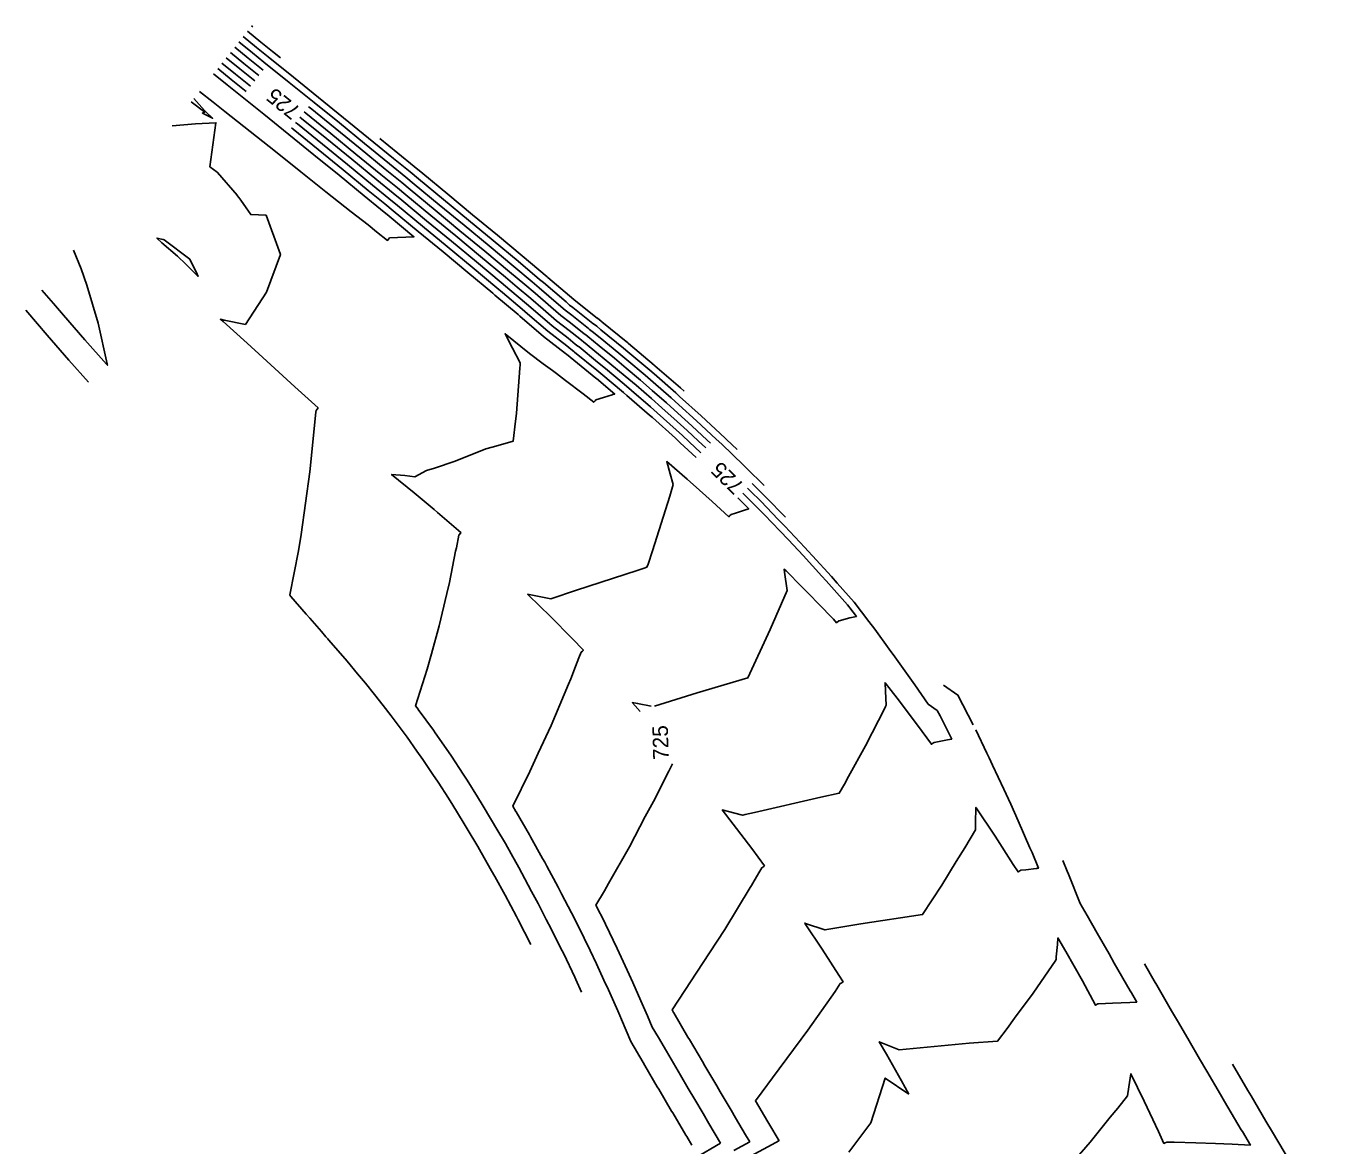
# Model space of a CAD drawing. Extents: x 1487507 to 1489130, y 497211 to 499439.
# Drawn here: x 1488436.5 to 1488637.2, y 499265.5 to 499439 of the extents above; entities that cross this region are included whole.
import ezdxf

# ---------------------------------------------------------------- set-up
doc = ezdxf.new("R2010")
doc.units = 0
for name, color, linetype in [('Prop CMT Ditch DDE', 7, 'Continuous'), ('Prop Drainage Ditch Flow Line', 7, 'Continuous'), ('Prop Drainage Structure Box Number Symbol CELL', 7, 'Continuous')]:
    doc.layers.add(name, color=color, linetype=linetype)

msp = doc.modelspace()

# ---------------------------------------------------------------- linework, layer by layer
at = {"layer": 'Prop CMT Ditch DDE'}
for points in [[(1488470.1, 499437.32), (1488472.2, 499435.62), (1488473.99, 499434.18), (1488477.89, 499431.04), (1488481.78, 499427.9), (1488485.66, 499424.75), (1488489.54, 499421.59), (1488493.41, 499418.43), (1488495.97, 499416.34), (1488497.28, 499415.26), (1488501.14, 499412.08), (1488504.99, 499408.89), (1488508.84, 499405.7), (1488512.68, 499402.5), (1488516.02, 499399.7), (1488516.63, 499399.19), (1488520.12, 499396.19), (1488520.67, 499395.71), (1488521.18, 499395.31), (1488524.28, 499392.88), (1488524.37, 499392.81), (1488524.86, 499392.42), (1488525.52, 499391.88), (1488529, 499389.05), (1488529.67, 499388.48), (1488533.08, 499385.62), (1488533.74, 499385.04), (1488537.1, 499382.11), (1488537.7, 499381.57), (1488541.06, 499378.54), (1488544.77, 499375.08), (1488544.97, 499374.9), (1488546.61, 499373.32)], [(1488471.62, 499438.8), (1488471.41, 499438.97)], [(1488473.22, 499432.1), (1488472.69, 499432.53), (1488470.89, 499433.97), (1488468.8, 499435.67)], [(1488469.45, 499436.49), (1488471.55, 499434.79), (1488473.34, 499433.35), (1488477.24, 499430.22), (1488481.13, 499427.08), (1488485.01, 499423.93), (1488488.89, 499420.77), (1488492.76, 499417.61), (1488495.31, 499415.51), (1488496.62, 499414.43), (1488500.49, 499411.25), (1488504.34, 499408.07), (1488508.19, 499404.87), (1488512.03, 499401.67), (1488514.87, 499399.29), (1488515.97, 499398.37), (1488518.93, 499395.82), (1488520, 499394.9), (1488520.99, 499394.13), (1488523.6, 499392.08), (1488523.76, 499391.95), (1488524.18, 499391.62), (1488525.4, 499390.63), (1488528.3, 499388.26), (1488529.54, 499387.22), (1488532.37, 499384.84), (1488533.6, 499383.76), (1488536.38, 499381.34), (1488537.57, 499380.27), (1488540.33, 499377.78), (1488543.38, 499374.94), (1488544.23, 499374.15), (1488547.61, 499370.89), (1488548.06, 499370.46), (1488550.79, 499367.74)], [(1488471.23, 499429.64), (1488470.72, 499430.05), (1488468.93, 499431.49), (1488466.83, 499433.2)], [(1488468.14, 499434.84), (1488470.24, 499433.14), (1488472.03, 499431.7), (1488472.56, 499431.28)], [(1488465.53, 499431.55), (1488467.62, 499429.84), (1488469.42, 499428.4), (1488473.31, 499425.27), (1488477.2, 499422.13), (1488481.08, 499418.98), (1488484.96, 499415.82), (1488488.83, 499412.66), (1488491.39, 499410.56), (1488492.7, 499409.49), (1488496.56, 499406.31), (1488496.57, 499406.3), (1488496.56, 499406.3), (1488492.79, 499406.11), (1488492.48, 499405.72), (1488490.78, 499407.06), (1488489.45, 499408.12), (1488486.86, 499410.17), (1488482.94, 499413.28), (1488479.03, 499416.38), (1488475.11, 499419.49), (1488471.19, 499422.6), (1488467.27, 499425.7), (1488465.47, 499427.13), (1488463.36, 499428.81)], [(1488466.18, 499432.37), (1488468.28, 499430.67), (1488470.07, 499429.23), (1488470.57, 499428.82)], [(1488462.48, 499427.71), (1488464.15, 499425.85), (1488464.31, 499425.67), (1488465.37, 499424.66), (1488463.8, 499425.46), (1488463.94, 499425.52), (1488464.11, 499425.59), (1488464.13, 499425.6), (1488464.16, 499425.6), (1488462.08, 499427.2)], [(1488479.56, 499425.63), (1488479.82, 499425.43), (1488483.7, 499422.28), (1488487.58, 499419.12), (1488491.45, 499415.96), (1488494, 499413.86), (1488495.32, 499412.78), (1488499.18, 499409.61), (1488503.03, 499406.42), (1488506.88, 499403.22), (1488510.72, 499400.02), (1488512.56, 499398.48), (1488514.65, 499396.73), (1488516.55, 499395.1), (1488518.66, 499393.28), (1488520.61, 499391.75), (1488522.23, 499390.48), (1488522.55, 499390.22), (1488522.81, 499390.02), (1488525.14, 499388.12), (1488526.91, 499386.68), (1488529.27, 499384.7), (1488530.95, 499383.28), (1488533.33, 499381.21), (1488534.94, 499379.8), (1488537.31, 499377.67), (1488538.87, 499376.26), (1488540.59, 499374.66), (1488541.75, 499373.58)], [(1488542.49, 499374.33), (1488541.98, 499374.8), (1488539.6, 499377.02), (1488537.44, 499378.97), (1488535.66, 499380.57), (1488533.47, 499382.48), (1488531.66, 499384.06), (1488529.4, 499385.96), (1488527.6, 499387.47), (1488525.27, 499389.38), (1488523.49, 499390.82), (1488523.16, 499391.09), (1488522.91, 499391.28), (1488520.8, 499392.94), (1488519.33, 499394.09), (1488517.74, 499395.46), (1488515.31, 499397.55), (1488513.71, 499398.89), (1488511.38, 499400.85), (1488507.53, 499404.05), (1488503.69, 499407.24), (1488499.83, 499410.43), (1488495.97, 499413.61), (1488494.66, 499414.69), (1488492.1, 499416.78), (1488488.23, 499419.95), (1488484.35, 499423.1), (1488480.47, 499426.25), (1488480.23, 499426.45)], [(1488459.14, 499423.5), (1488462.75, 499423.8), (1488465.89, 499423.96), (1488464.97, 499417.14), (1488466.09, 499416.3), (1488466.15, 499416.24), (1488469.17, 499412.73), (1488469.19, 499412.71), (1488469.21, 499412.68), (1488469.46, 499412.37), (1488469.76, 499411.96), (1488470.59, 499410.77), (1488471.3, 499409.73), (1488473.67, 499409.63), (1488475.7, 499404.14), (1488475.87, 499403.57), (1488473.71, 499397.69), (1488470.45, 499392.72), (1488467.17, 499393.39), (1488466.6, 499393.52), (1488467, 499393.16), (1488470.71, 499389.8), (1488473.16, 499387.57), (1488474.42, 499386.43), (1488478.13, 499383.06), (1488481.72, 499379.8), (1488481.41, 499379.4), (1488481.39, 499379.13), (1488480.42, 499369.86), (1488479.11, 499360.15), (1488478.67, 499357.65), (1488477.34, 499350.79), (1488477.46, 499350.59), (1488477.5, 499350.53), (1488479.89, 499347.84), (1488480.45, 499347.21), (1488482.23, 499345.12), (1488482.92, 499344.29), (1488483.22, 499343.97), (1488483.33, 499343.83), (1488485.18, 499341.72), (1488486.24, 499340.51), (1488487.84, 499338.59), (1488489.06, 499337.13), (1488490.46, 499335.38), (1488491.8, 499333.68), (1488493.02, 499332.08), (1488494.45, 499330.18), (1488495.49, 499328.74), (1488497.02, 499326.61), (1488497.92, 499325.32), (1488499.51, 499322.99), (1488500.29, 499321.8), (1488501.9, 499319.32), (1488502.59, 499318.22), (1488504.2, 499315.6), (1488504.82, 499314.57), (1488506.43, 499311.84), (1488506.99, 499310.88), (1488508.59, 499308.06), (1488509.1, 499307.15), (1488510.69, 499304.26), (1488512.42, 499300.98), (1488512.72, 499300.43), (1488514.67, 499296.61)], [(1488477.58, 499423.18), (1488477.85, 499422.95), (1488481.74, 499419.8), (1488485.62, 499416.65), (1488489.49, 499413.48), (1488492.04, 499411.39), (1488493.35, 499410.31), (1488497.21, 499407.13), (1488501.07, 499403.94), (1488504.92, 499400.75), (1488508.76, 499397.55), (1488509.1, 499397.26), (1488512.68, 499394.27), (1488512.97, 499394.01), (1488516.64, 499390.85), (1488520.04, 499388.19), (1488520.19, 499388.08), (1488520.74, 499387.63), (1488520.76, 499387.62), (1488524.75, 499384.37), (1488524.82, 499384.31), (1488527.65, 499381.93), (1488527.38, 499381.85), (1488527.25, 499381.81), (1488525.92, 499381.41), (1488524.75, 499381.04), (1488524.61, 499380.89), (1488524.41, 499380.66), (1488522.75, 499381.97), (1488520.04, 499384.03), (1488518.62, 499385.11), (1488518.03, 499385.55), (1488516.59, 499386.61), (1488514.44, 499388.19), (1488510.67, 499391.28), (1488511.83, 499389.04), (1488513, 499386.78), (1488513, 499386.58), (1488512.99, 499386.45), (1488512.95, 499385.94), (1488512.43, 499378.97), (1488512.34, 499378.08), (1488512.31, 499377.73), (1488511.91, 499374.6), (1488508.9, 499373.74), (1488508.66, 499373.68), (1488507.71, 499373.42), (1488502.93, 499371.51), (1488499.72, 499370.45), (1488498.53, 499370.08), (1488496.72, 499369.09), (1488495.15, 499369.3), (1488493.1, 499369.47), (1488496.57, 499366.64), (1488499.7, 499364.01), (1488500.21, 499363.57), (1488503.8, 499360.45), (1488503.83, 499360.43), (1488503.5, 499360.06), (1488503.5, 499360.06), (1488503.13, 499358.12), (1488503.02, 499357.59), (1488502.07, 499352.74), (1488501.66, 499351.01), (1488500.49, 499346), (1488499.28, 499341.68), (1488498.63, 499339.28), (1488496.82, 499333.6), (1488497.19, 499333.11), (1488497.23, 499333.06), (1488499.57, 499329.83), (1488499.84, 499329.45), (1488501.9, 499326.47), (1488502.37, 499325.79), (1488504.19, 499323.02), (1488504.8, 499322.08), (1488506.41, 499319.5), (1488507.15, 499318.31), (1488508.59, 499315.9), (1488509.41, 499314.51), (1488510.72, 499312.26), (1488511.61, 499310.68), (1488512.8, 499308.56), (1488513.75, 499306.83), (1488514.79, 499304.87), (1488515.81, 499302.96), (1488517.05, 499300.53), (1488517.82, 499299.07), (1488519.28, 499296.11), (1488519.75, 499295.16), (1488521.46, 499291.57), (1488521.62, 499291.23), (1488522.53, 499289.25)], [(1488540.27, 499372.09), (1488537.8, 499374.38), (1488537.41, 499374.75), (1488537.06, 499375.07), (1488533.5, 499378.27), (1488533.05, 499378.66), (1488529.54, 499381.72), (1488528.99, 499382.18), (1488525.52, 499385.1), (1488524.88, 499385.62), (1488521.44, 499388.42), (1488521.34, 499388.5), (1488520.87, 499388.88), (1488520.23, 499389.38), (1488517.31, 499391.66), (1488514.16, 499394.37), (1488513.34, 499395.09), (1488510.25, 499397.67), (1488509.41, 499398.37), (1488505.57, 499401.57), (1488501.72, 499404.77), (1488497.87, 499407.96), (1488494.01, 499411.13), (1488492.69, 499412.21), (1488490.14, 499414.31), (1488486.27, 499417.47), (1488482.39, 499420.63), (1488478.51, 499423.78), (1488478.24, 499423.99)], [(1488438.96, 499398.04), (1488440.74, 499395.95), (1488442.27, 499394.17), (1488445.61, 499390.33), (1488448.97, 499386.53), (1488449.09, 499386.4), (1488449.05, 499386.63), (1488447.66, 499392.92), (1488445.92, 499398.78), (1488445.01, 499401.33), (1488443.84, 499404.21)], [(1488436.47, 499394.91), (1488438.26, 499392.81), (1488439.78, 499391.04), (1488443.12, 499387.2), (1488446.14, 499383.78)], [(1488539.57, 499265.55), (1488538.8, 499266.86), (1488538.67, 499267.07), (1488536.64, 499270.54), (1488536.46, 499270.83), (1488534.47, 499274.22), (1488534.25, 499274.59), (1488532.31, 499277.9), (1488532.04, 499278.36), (1488530.14, 499281.59), (1488528.69, 499285.03), (1488528.44, 499285.62), (1488528.12, 499286.33), (1488526.67, 499289.63), (1488525.97, 499291.13), (1488524.83, 499293.62), (1488523.84, 499295.68), (1488522.93, 499297.59), (1488521.66, 499300.12), (1488520.95, 499301.55), (1488519.43, 499304.48), (1488518.91, 499305.49), (1488517.15, 499308.76), (1488516.81, 499309.41), (1488516.49, 499309.97), (1488514.63, 499313.3), (1488514.44, 499313.64), (1488512.39, 499317.17), (1488512.35, 499317.24), (1488511.86, 499318.07), (1488514.53, 499323.46), (1488515.78, 499326.26), (1488517.8, 499330.58), (1488520.48, 499336.95), (1488520.85, 499337.81), (1488521.58, 499339.7), (1488522.11, 499341.04), (1488522.45, 499341.91), (1488522.64, 499342.09), (1488522.81, 499342.25), (1488521.06, 499344.07), (1488517.71, 499347.45), (1488514.31, 499350.78), (1488514.17, 499350.91), (1488514.39, 499350.86), (1488517.75, 499350.2), (1488521.75, 499351.52), (1488531.13, 499354.59), (1488532.2, 499354.95), (1488532.65, 499355.1), (1488532.81, 499355.55), (1488533.48, 499357.64), (1488536.21, 499366.08), (1488536.73, 499367.92), (1488536.25, 499369.58), (1488535.7, 499371.45), (1488538.85, 499368.73), (1488540.77, 499367.03), (1488542.76, 499365.27), (1488545.34, 499362.91), (1488545.45, 499363.03), (1488545.7, 499363.26), (1488546.34, 499363.48), (1488548.05, 499364.03), (1488548.09, 499364.05), (1488548.42, 499364.15), (1488546.74, 499365.83)], [(1488548.22, 499367.33), (1488548.64, 499366.91), (1488550.31, 499365.25), (1488552.91, 499362.56), (1488554, 499361.45), (1488557.11, 499358.14), (1488557.63, 499357.59), (1488558.28, 499356.87), (1488561.2, 499353.67), (1488562.12, 499352.63), (1488564.71, 499349.7), (1488567, 499346.67), (1488567.91, 499345.47), (1488570.18, 499342.39), (1488571.05, 499341.2), (1488572.83, 499338.7), (1488574.12, 499336.89), (1488576.21, 499333.85), (1488577.6, 499332.88), (1488578.03, 499332.05), (1488579.85, 499328.45), (1488579.82, 499328.44), (1488579.48, 499328.38), (1488579.18, 499328.32), (1488577.12, 499327.95), (1488577, 499327.86), (1488576.71, 499327.65), (1488574.55, 499330.61), (1488571.39, 499334.79), (1488569.52, 499337.19), (1488569.59, 499335.87), (1488569.69, 499333.71), (1488569.59, 499333.5), (1488569.51, 499333.35), (1488566.48, 499327.43), (1488563.85, 499322.65), (1488563.24, 499321.5), (1488562.43, 499320.07), (1488559.57, 499319.46), (1488549.29, 499317.07), (1488547.88, 499316.75), (1488547.49, 499316.65), (1488547.26, 499316.71), (1488544.3, 499317.49), (1488546, 499315.3), (1488548.87, 499311.51), (1488550.84, 499308.82), (1488550.72, 499308.73), (1488550.44, 499308.52), (1488550.14, 499308.01), (1488549.24, 499306.5), (1488548.83, 499305.79), (1488548.61, 499305.45), (1488544.72, 499298.97), (1488542.35, 499295.33), (1488536.57, 499286.53), (1488536.75, 499286.12), (1488536.77, 499286.07), (1488536.79, 499286.04), (1488539, 499282.29), (1488539.22, 499281.91), (1488541.23, 499278.5), (1488541.62, 499277.83), (1488543.46, 499274.72), (1488544, 499273.79), (1488545.68, 499270.94), (1488546.36, 499269.78), (1488547.91, 499267.16), (1488548.57, 499266.04)], [(1488554.11, 499362.84), (1488551.07, 499365.97), (1488550.34, 499366.69), (1488548.96, 499368.08)], [(1488578.59, 499336.81), (1488580.81, 499335.27), (1488583.16, 499330.65)], [(1488583.55, 499329.87), (1488585.3, 499326.29), (1488585.64, 499325.58), (1488586.18, 499324.43), (1488587.93, 499320.7), (1488588.99, 499318.37), (1488590.15, 499315.79), (1488591.96, 499311.6), (1488592.28, 499310.87), (1488593.28, 499308.45), (1488593.09, 499308.42), (1488592.91, 499308.4), (1488591.31, 499308.22), (1488590.53, 499308.14), (1488590.22, 499307.94), (1488590.11, 499307.87), (1488589.38, 499309.03), (1488586.55, 499313.43), (1488583.64, 499317.79), (1488583.58, 499317.88), (1488583.58, 499317.83), (1488583.58, 499317.75), (1488583.54, 499315.57), (1488583.51, 499314.39), (1488581.87, 499311.61), (1488580.54, 499309.5), (1488578.3, 499305.83), (1488575.34, 499301.28), (1488565.78, 499299.83), (1488560.2, 499298.88), (1488557.2, 499299.9), (1488557.09, 499299.94), (1488557.14, 499299.86), (1488559.78, 499295.9), (1488562.36, 499291.89), (1488563.01, 499290.84), (1488562.7, 499290.64), (1488562.59, 499290.58), (1488561.77, 499289.37), (1488557.54, 499283.36), (1488552.09, 499275.99), (1488550.5, 499273.8), (1488549.45, 499272.42), (1488551.38, 499269.15), (1488551.51, 499268.92), (1488553.11, 499266.21)], [(1488597.06, 499309.64), (1488597.74, 499308.01), (1488597.93, 499307.53), (1488599.74, 499302.99), (1488600.8, 499301.14), (1488602.38, 499298.37), (1488604.2, 499295.19), (1488605.02, 499293.75), (1488607.5, 499289.44), (1488607.68, 499289.13), (1488608.5, 499287.7), (1488607.44, 499287.67), (1488604.74, 499287.56), (1488602.57, 499287.46), (1488602.49, 499287.42), (1488602.13, 499287.23), (1488600.07, 499291.01), (1488597.5, 499295.57), (1488596.29, 499297.65), (1488596.21, 499296.61), (1488596.04, 499294.74), (1488596.01, 499294.37), (1488595.99, 499294.18), (1488592.43, 499289.07), (1488589.57, 499285.2), (1488588.43, 499283.61), (1488586.94, 499281.66), (1488582.56, 499281.32), (1488571.68, 499280.29), (1488571.19, 499280.5), (1488568.63, 499281.55), (1488569.73, 499279.66), (1488572.07, 499275.52), (1488573.2, 499273.43)], [(1488597.19, 499261.29), (1488601.26, 499266.02), (1488604.39, 499269.86), (1488605.57, 499271.28), (1488607.06, 499273.16), (1488607.29, 499274.6), (1488607.6, 499276.61), (1488609.66, 499272.38), (1488611.88, 499267.64), (1488612.71, 499265.81), (1488612.88, 499265.89), (1488613.16, 499266.02), (1488614.31, 499265.98), (1488617.62, 499265.92), (1488620.69, 499265.8), (1488623.27, 499265.71), (1488626.09, 499265.55), (1488624.85, 499267.64), (1488624.67, 499267.94), (1488622.09, 499272.32), (1488621.47, 499273.38), (1488619.34, 499277), (1488618.23, 499278.9), (1488616.61, 499281.68), (1488614.95, 499284.55), (1488613.9, 499286.35), (1488611.61, 499290.32), (1488611.21, 499291.01), (1488609.71, 499293.62)], [(1488563.92, 499264.44), (1488567.3, 499268.99), (1488569.56, 499275.94), (1488573.2, 499273.43)], [(1488548.57, 499266.04), (1488546.1, 499264.71)], [(1488553.11, 499266.21), (1488553.08, 499266.19), (1488552.03, 499265.63), (1488547.99, 499263.46)]]:
    msp.add_lwpolyline(points, dxfattribs=at)
msp.add_lwpolyline([(1488461.88, 499402.81), (1488457.89, 499405.82), (1488457.73, 499405.88), (1488456.77, 499406.1), (1488457.53, 499405.37), (1488459.97, 499403.3), (1488461.26, 499402.03), (1488463.14, 499400.14), (1488463, 499400.49)], close=True, dxfattribs=at)
at = {"layer": 'Prop Drainage Ditch Flow Line'}
for points in [[(1488475.89, 499434), (1488474.65, 499435), (1488472.85, 499436.44), (1488470.76, 499438.14)], [(1488471.9, 499430.46), (1488471.38, 499430.88), (1488469.58, 499432.32), (1488467.49, 499434.02)], [(1488541.01, 499372.84), (1488539.2, 499374.52), (1488538.14, 499375.51), (1488537.18, 499376.37), (1488534.22, 499379.04), (1488533.19, 499379.93), (1488530.25, 499382.5), (1488529.13, 499383.44), (1488526.21, 499385.89), (1488525.01, 499386.87), (1488522.13, 499389.22), (1488521.95, 499389.36), (1488521.55, 499389.68), (1488520.42, 499390.56), (1488517.99, 499392.47), (1488515.36, 499394.74), (1488514, 499395.91), (1488511.41, 499398.08), (1488510.07, 499399.2), (1488506.23, 499402.4), (1488502.38, 499405.59), (1488498.52, 499408.78), (1488494.66, 499411.96), (1488493.35, 499413.04), (1488490.8, 499415.13), (1488486.92, 499418.3), (1488483.05, 499421.45), (1488479.16, 499424.6), (1488478.9, 499424.81)], [(1488538.39, 499382.36), (1488537.83, 499382.87), (1488537.82, 499382.88), (1488533.88, 499386.31), (1488533.78, 499386.4), (1488529.81, 499389.75), (1488529.69, 499389.84), (1488525.65, 499393.13), (1488525.55, 499393.22), (1488524.98, 499393.68), (1488524.96, 499393.69), (1488521.37, 499396.5), (1488521.35, 499396.52), (1488521.32, 499396.55), (1488517.29, 499400.01), (1488517.17, 499400.11), (1488513.34, 499403.32), (1488509.5, 499406.52), (1488505.65, 499409.72), (1488501.79, 499412.9), (1488497.93, 499416.08), (1488496.62, 499417.16), (1488494.07, 499419.26), (1488491.3, 499421.52)], [(1488533.82, 499333.58), (1488540.4, 499335.64), (1488548.27, 499337.94), (1488551.71, 499345.44), (1488554.36, 499351.51), (1488553.96, 499354.31), (1488553.89, 499354.79), (1488554.18, 499354.51), (1488556.64, 499352.05), (1488557.89, 499350.8), (1488559.18, 499349.47), (1488561.54, 499347.04), (1488562.01, 499346.48), (1488562.34, 499346.76), (1488562.39, 499346.8), (1488564.05, 499347.23), (1488564.84, 499347.42), (1488565.07, 499347.48), (1488564.07, 499348.8), (1488563.9, 499349.02), (1488563.71, 499349.24), (1488560.4, 499352.98), (1488559.72, 499353.73), (1488556.84, 499356.89), (1488554.56, 499359.31), (1488553.22, 499360.73), (1488550.83, 499363.19), (1488549.54, 499364.52), (1488547.48, 499366.58)], [(1488531.61, 499332.73), (1488530.82, 499333.63), (1488530.36, 499334.13), (1488531.2, 499333.98), (1488533.31, 499333.56)], [(1488544.04, 499265.83), (1488542.24, 499268.9), (1488541.34, 499270.43), (1488540.05, 499272.63), (1488539.04, 499274.33), (1488537.85, 499276.36), (1488536.74, 499278.25), (1488535.66, 499280.09), (1488534.41, 499282.2), (1488533.45, 499283.83), (1488532.72, 499285.57), (1488531.72, 499287.91), (1488530.45, 499290.75), (1488529.91, 499291.96), (1488528.35, 499295.34), (1488528.04, 499296.01), (1488526.22, 499299.78), (1488526.1, 499300.03), (1488524.75, 499302.72), (1488526.06, 499304.93), (1488526.68, 499306.09), (1488529.93, 499311.78), (1488532.39, 499316.49), (1488533.65, 499318.78), (1488536.03, 499323.5), (1488536.33, 499324.09), (1488536.61, 499324.65)], [(1488623.33, 499278.07), (1488625.72, 499273.99), (1488626.2, 499273.18), (1488628.51, 499269.25), (1488629.54, 499267.53), (1488631.33, 499264.5), (1488632.87, 499261.92), (1488634.17, 499259.73), (1488635.02, 499255.94), (1488635.39, 499254.31), (1488636.34, 499249.72), (1488636.52, 499248.88), (1488636.67, 499248.1), (1488637.2, 499245.34)], [(1488494.02, 499219.53), (1488495.7, 499221.71), (1488498.78, 499225.69), (1488501.9, 499229.64), (1488504.13, 499232.41), (1488505.15, 499233.68), (1488506.46, 499235.17), (1488508.93, 499238), (1488511.23, 499240.43), (1488512.89, 499242.18), (1488515.17, 499244.41), (1488517.02, 499246.21), (1488519.27, 499248.24), (1488521.32, 499250.08), (1488523.67, 499251.98), (1488525.81, 499253.72), (1488528.45, 499255.69), (1488530.45, 499257.19), (1488533.52, 499259.3), (1488535.23, 499260.48), (1488538.66, 499262.64), (1488540.14, 499263.57), (1488544.04, 499265.83)]]:
    msp.add_lwpolyline(points, dxfattribs=at)

# ---------------------------------------------------------------- texts
at = {"layer": 'Prop Drainage Structure Box Number Symbol CELL'}
for rotation, p in [(141.0344, (1488479.15, 499426.15)), (135.3073, (1488547.84, 499367.87)), (91.6134, (1488536.02, 499325.28))]:
    msp.add_text('725', height=2.4, rotation=rotation, dxfattribs=at).set_placement(p)

doc.saveas('drawing.dxf')
